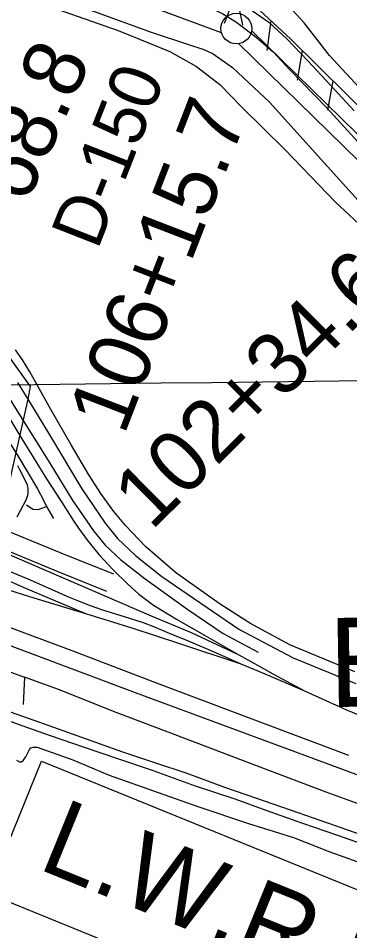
# Model space of a CAD drawing. Extents: x 3715084 to 3753216, y 488173 to 513963.
# Drawn here: x 3722098 to 3722638, y 498796 to 500282 of the extents above; entities that cross this region are included whole.
import ezdxf

# ---------------------------------------------------------------- set-up
doc = ezdxf.new("R2010")
doc.units = 0
for name, color, linetype in [('V-FLOD-BASE', 7, 'Continuous'), ('V-GRID-MAJR', 7, 'Continuous'), ('V-LEVE-TOET', 7, 'Continuous'), ('V-RAIL-TRAK', 7, 'Continuous'), ('V-RIVR-RANG', 7, 'Continuous'), ('V-RIVR-RANG-IDEN', 7, 'Continuous'), ('V-ROAD-CNTR', 7, 'Continuous'), ('V-RRAP-FSHR', 7, 'Continuous'), ('V-SITE-OTLN', 7, 'Continuous'), ('V-SITE-VEGE', 7, 'Continuous'), ('V-SURV-IDEN', 7, 'Continuous'), ('V-SURV-LINE', 7, 'Continuous'), ('V-TOPO-GNAM-IDEN', 7, 'Continuous'), ('V-TOPO-SHOR', 7, 'Continuous'), ('V-TOPO-WATR-IDEN', 7, 'Continuous')]:
    doc.layers.add(name, color=color, linetype=linetype)

msp = doc.modelspace()

# ---------------------------------------------------------------- linework, layer by layer
at = {"layer": 'V-FLOD-BASE'}
msp.add_lwpolyline([(3721354.051, 500735.405), (3721503.6550000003, 500674.19), (3721616.043, 500624.451), (3721750.253, 500566.103), (3721896.302, 500502.113), (3722014.554, 500452.484), (3722117.367, 500407.97500000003), (3722199.265, 500372.09), (3722243.313, 500357.139), (3722302.3140000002, 500338.863), (3722369.511, 500316.685), (3722399.9790000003, 500304.18200000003), (3722430.949, 500288.982), (3722451.484, 500276.74100000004), (3722460.182, 500270.13800000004), (3722485.358, 500251.219), (3722513.794, 500226.946), (3722540.06, 500198.12), (3722600.495, 500136.261), (3722650.953, 500080.901)], dxfattribs=at)
at = {"layer": 'V-GRID-MAJR'}
msp.add_spline([(3719277.161, 499651.167), (3724559.356, 499715.322), (3729841.541, 499780.245), (3735123.717, 499845.93700000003), (3740405.883, 499912.396), (3745688.039, 499979.624), (3750970.185, 500047.621), (3750970.186, 500047.621)], degree=3, dxfattribs=at)
at = {"layer": 'V-LEVE-TOET'}
for points in [[(3720179.593, 501167.86100000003), (3720304.218, 501115.194), (3720443.535, 501049.273), (3720609.5270000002, 500980.25200000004), (3720771.923, 500910.712), (3720950.632, 500837.42), (3721109.843, 500769.172), (3721268.537, 500704.525), (3721370.967, 500656.39900000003), (3721469.29, 500610.901), (3721591.1750000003, 500559.988), (3721710.311, 500511.278), (3721874.223, 500433.194), (3722033.844, 500367.20900000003), (3722177.073, 500309.034), (3722316.0870000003, 500258.89900000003), (3722373.752, 500239.697), (3722400.0810000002, 500231.175), (3722415.562, 500223.8), (3722446.661, 500201.835), (3722506.846, 500145.233), (3722601.332, 500040.56), (3722665.858, 499969.152)], [(3722479.5700000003, 500293.832), (3722505.856, 500275.83400000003), (3722535.2490000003, 500248.64900000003), (3722569.545, 500212.757), (3722605.481, 500173.74100000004), (3722644.643, 500131.175)]]:
    msp.add_lwpolyline(points, dxfattribs=at)
at = {"layer": 'V-RAIL-TRAK'}
for points in [[(3720331.13, 500168), (3720500.807, 500094.989), (3720658.671, 500026.267), (3720805.599, 499963.2), (3720958.009, 499896.628), (3721103.132, 499833.527), (3721225.492, 499781.273), (3721513.0500000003, 499654.11600000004), (3721780.551, 499537.855), (3722047.557, 499423.843), (3722314.5810000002, 499308.928), (3722379.616, 499281.74700000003), (3722429.239, 499258.33), (3722456.9990000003, 499245.776), (3722487.551, 499228.76300000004), (3722512.631, 499214.804), (3722564.145, 499186.912)], [(3720714.538, 499959.20900000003), (3720850.106, 499900.43700000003), (3721073.913, 499804.097), (3721268.176, 499719.376), (3721405.556, 499660.18700000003), (3721526.562, 499607.905), (3721636.1920000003, 499560.82), (3721735.387, 499516.693), (3721849.585, 499466.538), (3722018.793, 499394.422), (3722110.242, 499354.207), (3722207.811, 499312.756)], [(3720703.555, 499931.928), (3720820.0100000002, 499881.815), (3721010.196, 499797.919), (3721214.484, 499707.973), (3721455.126, 499604.284), (3721733.9960000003, 499483.278), (3721884.524, 499420.732), (3721914.556, 499407.32), (3721942.282, 499396.568), (3721965.889, 499388.898), (3722002.653, 499377.417), (3722048.063, 499362.043), (3722096.168, 499347.17), (3722123.409, 499338.21400000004), (3722207.811, 499312.756), (3722284.511, 499288.954), (3722357.153, 499265.074), (3722460.44, 499230.952)], [(3721019.975, 499840.966), (3721233.3170000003, 499749.387), (3721365.702, 499691.908), (3721533.556, 499619.767), (3721664.5870000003, 499562.264), (3721833.361, 499489.23600000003), (3722021.693, 499408.01), (3722064.455, 499389.427), (3722113.566, 499369.16000000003), (3722180.9080000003, 499339.31200000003), (3722194.542, 499334.159), (3722214.9990000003, 499325.978), (3722235.441, 499318.699), (3722279.012, 499305.092), (3722301.7, 499298.30700000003), (3722318.5160000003, 499291.86), (3722343.987, 499281.06700000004), (3722374.453, 499268.564), (3722419.029, 499249.563), (3722460.44, 499230.952), (3722502.274, 499213.704), (3722564.145, 499186.912), (3722627.401, 499158.343), (3722685.167, 499133.73)], [(3722077.2430000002, 499641.419), (3722104.254, 499597.27), (3722144.294, 499532.162), (3722168.469, 499494.727), (3722188.0130000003, 499463.517), (3722196.363, 499451.495), (3722210.723, 499431.919), (3722230.122, 499408.37700000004), (3722252.693, 499383.993), (3722276.14, 499360.982), (3722294.509, 499344.186), (3722318.305, 499326.594), (3722355.74, 499303.396), (3722399.987, 499278.075), (3722456.9990000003, 499245.776)], [(3722067.824, 499158.664), (3722140.491, 499133.208), (3722193.643, 499113.919), (3722267.676, 499087.814), (3722319.892, 499070.311), (3722372.335, 499052.59), (3722433.89, 499030.306), (3722485.669, 499011.89400000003), (3722553.1, 498989.045), (3722603.286, 498971.506), (3722665.052, 498949.901)], [(3722055.63, 499147.603), (3722105.589, 499130.06), (3722150.328, 499114.22000000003), (3722205.73, 499095.20300000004), (3722259.771, 499076.609), (3722314.481, 499058.255), (3722386.0300000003, 499032.325), (3722450.724, 499011.001), (3722500.923, 498992.786), (3722560.88, 498971.37200000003), (3722617.423, 498951.699), (3722674.64, 498932.039)]]:
    msp.add_lwpolyline(points, dxfattribs=at)
at = {"layer": 'V-RIVR-RANG'}
msp.add_line((3722433.9820000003, 500274.22300000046), (3722666.508, 500870.4910000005), dxfattribs=at)
at = {"layer": 'V-ROAD-CNTR'}
for points in [[(3720251.6783072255, 500219.6346124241), (3720308.6642738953, 500190.63727090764), (3720375.5829743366, 500156.585244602), (3720540.0271052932, 500080.3801856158), (3720665.4403785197, 500024.9046668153), (3720706.9172404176, 500008.49372954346), (3720843.506440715, 499949.191713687), (3721011.286575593, 499878.08507093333), (3721152.799076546, 499819.4778442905), (3721290.7920817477, 499757.6898569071), (3721410.819299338, 499707.1985587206), (3721530.781916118, 499653.69657235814), (3721581.56070035, 499631.33057269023), (3721759.180182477, 499553.09836033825), (3721970.3879949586, 499460.0875790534), (3722057.2200908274, 499424.38022048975), (3722162.6836148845, 499381.0096295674), (3722241.9095104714, 499349.3547025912)], [(3722097.237, 499688.938), (3722113.718, 499661.825), (3722147.387, 499606.431), (3722201.794, 499515.794), (3722239.807, 499459.737), (3722259.437, 499434.798), (3722289.393, 499406.636), (3722331.762, 499373.237), (3722457.2290000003, 499287.37700000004), (3722545.6920000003, 499240.492), (3722647.742, 499198.653)], [(3724721.5925178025, 498318.2013374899), (3722898.611163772, 498957.6830585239), (3722289.22838254, 499183.4286070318), (3721129.602701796, 499619.490734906)], [(3722097.154913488, 499553.62691189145), (3722100.310142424, 499547.42194799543), (3722111.263800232, 499525.88859402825), (3722112.517386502, 499522.5469335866), (3722113.3979872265, 499519.12012826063), (3722113.9057156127, 499515.61753823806), (3722114.0341783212, 499512.0866489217), (3722113.7859046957, 499508.55748530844), (3722113.154824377, 499505.0625551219), (3722112.1545054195, 499501.67248335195), (3722110.8440464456, 499498.5110233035), (3722095.649951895, 499469.77940974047)], [(3722081.915745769, 499446.66214088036), (3722173.9543851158, 499408.8123704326), (3722253.040489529, 499377.21329740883)]]:
    msp.add_lwpolyline(points, dxfattribs=at)
at = {"layer": 'V-RRAP-FSHR'}
for p, q in [((3722453.522, 500318.373), (3722463.264, 500270.52400000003)), ((3722509.4050000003, 500277.787), (3722502.596, 500229.433)), ((3722560.057, 500229.482), (3722551.8310000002, 500181.349)), ((3722609.815, 500180.24700000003), (3722601.589, 500132.114))]:
    msp.add_line(p, q, dxfattribs=at)
for points in [[(3724699.7800000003, 499231.582), (3724234.565, 499410.511), (3724074.774, 499465.947), (3723910.948, 499525.384), (3723785.557, 499586.533), (3722795.661, 500019.571), (3722760.251, 500033.657), (3722724.847, 500066.423), (3722541.517, 500247.827), (3722476.702, 500308.298), (3722393.071, 500344.648), (3721960.203, 500508.445), (3721362.184, 500763.99100000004), (3720460.911, 501156.501), (3720298.304, 501222.873), (3720229.921, 501264.912), (3720222.529, 501299.679)], [(3722824.319, 500007.034), (3722795.661, 500019.571), (3722760.251, 500033.657), (3722724.847, 500066.423), (3722541.517, 500247.827), (3722476.702, 500308.298), (3722393.071, 500344.648), (3721960.203, 500508.445), (3721362.184, 500763.99100000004), (3720460.911, 501156.501), (3720298.304, 501222.873), (3720229.921, 501264.912), (3720222.529, 501299.679)]]:
    msp.add_lwpolyline(points, dxfattribs=at)
at = {"layer": 'V-SITE-OTLN'}
msp.add_lwpolyline([(3721610.727, 500476.558), (3721508.9, 500234.186), (3721552.287, 500172.613), (3721570.951, 500156.45), (3721741.701, 500056.927), (3721760.257, 500046.26900000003), (3721989.84, 499845.09), (3722040.461, 499789.161), (3722117.748, 499682.35000000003), (3722113.718, 499661.825), (3722086.94, 499540.62200000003), (3722077.251, 499496.20900000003), (3722068.324, 499483.19), (3722044.823, 499464.39), (3722009.753, 499474.732), (3721224.957, 499821.32300000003), (3721022.99, 499907.071)], dxfattribs=at)
at = {"layer": 'V-SITE-VEGE'}
for p, q in [((3722116.523, 499091.35499999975), (3722118.727, 499094.103)), ((3722118.727, 499094.103), (3722122.543, 499095.07800000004)), ((3722122.543, 499095.07800000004), (3722125.696, 499095.365)), ((3722125.696, 499095.365), (3722129.088, 499094.977)), ((3722129.088, 499094.977), (3722186.77, 499074.64900000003)), ((3722106.7770000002, 499074.137), (3722110.656, 499079.701)), ((3722110.656, 499079.701), (3722113.111, 499084.936)), ((3722113.111, 499084.936), (3722116.523, 499091.35499999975)), ((3722095.271, 499074.143), (3722100.293, 499071.081)), ((3722100.293, 499071.081), (3722103.447, 499071.368)), ((3722103.447, 499071.368), (3722106.7770000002, 499074.137)), ((3722186.77, 499074.64899999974), (3722207.69, 499065.8)), ((3722207.69, 499065.8), (3722246.342, 499049.846)), ((3722246.342, 499049.8459999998), (3722390.554, 498998.68499999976)), ((3722390.554, 498998.685), (3722472.972, 498970.707)), ((3722472.972, 498970.707), (3722546.038, 498947.9659999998)), ((3722546.038, 498947.9659999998), (3722605.3540000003, 498924.73499999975)), ((3722605.3540000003, 498924.73499999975), (3722695.298, 498892.39099999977))]:
    msp.add_line(p, q, dxfattribs=at)
for points in [[(3721724.012, 500148.555), (3721730.062, 500186.115), (3721748.719, 500248.733), (3721783.838, 500323.392), (3721808.904, 500381.169), (3721821.0500000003, 500406.666), (3721826.742, 500415.798), (3721833.404, 500421.338), (3721839.691, 500422.811), (3721845.989, 500423.835), (3721859.5530000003, 500422.288), (3721908.647, 500402.922), (3722063.407, 500331.433), (3722260.987, 500262.114), (3722345.111, 500227.626), (3722387.9760000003, 500203.632), (3722426.435, 500174.134), (3722462.795, 500136.48), (3722532.22, 500068.324), (3722614.169, 499982.364), (3722668.3510000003, 499932.865)], [(3722659.2460000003, 500161.97500000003), (3722604.484, 500221.265), (3722563.241, 500274.777), (3722531.0670000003, 500309.693)], [(3722645.903, 499217.571), (3722539.941, 499261.57), (3722475.202, 499296.878), (3722424.965, 499328.853), (3722354.063, 499379.836), (3722305.4390000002, 499421.76900000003), (3722272.747, 499456.335), (3722253.8170000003, 499478.984), (3722233.44, 499506.566), (3722212.9760000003, 499538.66000000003), (3722184.077, 499587.286), (3722151.397, 499644.863), (3722126.643, 499689.055), (3722116.8370000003, 499706.463), (3722105.182, 499726.093), (3722093.598, 499742.113)]]:
    msp.add_lwpolyline(points, dxfattribs=at)
at = {"layer": 'V-SURV-LINE'}
for points in [[(3722429.1476082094, 500258.06374399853), (3722229.3442902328, 500332.4302392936)], [(3722477.8635045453, 500261.8978983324), (3722721.541392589, 500023.26420227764)], [(3722700.555658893, 500001.8259416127), (3722456.8780626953, 500240.4593518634)]]:
    msp.add_lwpolyline(points, dxfattribs=at)
msp.add_circle((3722453.10042, 500265.15374000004), 25, dxfattribs=at)
at = {"layer": 'V-TOPO-SHOR'}
for points in [[(3721534.867, 500138.745), (3721627.918, 500084.422), (3721683.912, 500054.01900000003), (3721701.2260000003, 500043.06), (3721722.7260000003, 500027.735), (3721782.13, 499979.95300000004), (3721856.4420000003, 499921.851), (3721936.762, 499853.602), (3721996.718, 499794.884), (3722024.849, 499754.71400000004), (3722057.267, 499705.048), (3722098.552, 499638.791), (3722149.3570000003, 499557.664), (3722185.734, 499497.813), (3722220.5640000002, 499447.166), (3722239.813, 499424.271), (3722264.897, 499400.463), (3722304.4930000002, 499369.065), (3722374.1950000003, 499319.42600000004), (3722431.721, 499280.50200000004), (3722488.741, 499250.12)], [(3721839.077, 499881.84), (3721888.311, 499847.204), (3721919.27, 499820.086), (3721950.33, 499787.84), (3721970.286, 499763.934), (3721998.299, 499729.92100000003), (3722021.185, 499695.80700000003), (3722051.272, 499642.678), (3722099.238, 499566.97000000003), (3722129.631, 499515.897), (3722139.563, 499497.272), (3722144.204, 499487.10000000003), (3722155.526, 499467.476)], [(3722636.079, 499081.811), (3722482.95, 499138.895), (3722328.8910000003, 499197.314), (3722190.278, 499250.163), (3722022.6040000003, 499312.833), (3721879.015, 499366.489), (3721708.1580000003, 499430.452), (3721634.572, 499456.57), (3721492.307, 499511.604), (3721352.3510000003, 499563.976), (3721225.396, 499620.656), (3721105.403, 499667.092), (3720991.829, 499713.396)], [(3722111.6550000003, 499489.897), (3722122.057, 499482.572), (3722130.96, 499482.058), (3722135.037, 499483.504), (3722144.204, 499487.10000000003)], [(3721798.463, 499324.14900000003), (3721941.3540000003, 499270.378), (3722075.3850000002, 499221.052), (3722108.549, 499209.05100000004), (3722106.054, 499164.435)], [(3723779.79, 498603.51900000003), (3723676.352, 498639.375), (3723546.474, 498683.81700000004), (3723422.0500000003, 498726.108), (3723285.348, 498773.579), (3723159.119, 498815.835), (3723009.218, 498869.37), (3722849.349, 498924.971), (3722747.06, 498965.88), (3722688.86, 498989.581), (3722599.362, 499022.163), (3722487.574, 499064.243), (3722342.148, 499119.668), (3722257.627, 499151.441), (3722163.974, 499188.905), (3722108.549, 499209.05100000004)]]:
    msp.add_lwpolyline(points, dxfattribs=at)
at = {"layer": 'V-TOPO-WATR-IDEN'}
msp.add_line((3722001.16819057, 498876.8247659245), (3722696.8715213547, 498593.4551917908), dxfattribs=at)
msp.add_lwpolyline([(3721781.516564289, 498994.9219852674), (3722081.6616703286, 498938.205217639), (3722136.2556967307, 499072.23799779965), (3722727.61375126, 498831.3669422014), (3722673.019724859, 498697.33416204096), (3722936.5255493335, 498524.4654973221)], dxfattribs=at)

# ---------------------------------------------------------------- texts
at = {"layer": 'V-RIVR-RANG-IDEN'}
msp.add_text('D-150', height=83, rotation=68.55432571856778, dxfattribs=at).set_placement((3722227.152143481, 499903.27871804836))
at = {"layer": 'V-SURV-IDEN'}
for s, height, rotation, p in [('108+68.8', 99.99999999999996, 65.90138889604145, (3721988.143408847, 499701.5846143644)), ('106+15.7', 100.00000000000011, 68.88805557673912, (3722270.2480142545, 499601.36499050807)), ('102+34.6', 99.99999999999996, 44.90194442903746, (3722315.0290362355, 499446.4662424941))]:
    msp.add_text(s, height=height, rotation=rotation, dxfattribs=at).set_placement(p)
at = {"layer": 'V-TOPO-GNAM-IDEN'}
msp.add_text('Braithwaite', height=145.00000199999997, rotation=0.9179915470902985, dxfattribs=at).set_placement((3722604.132, 499160.358))
at = {"layer": 'V-TOPO-WATR-IDEN'}
msp.add_text('L.W.R.P.', height=124.49949300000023, rotation=337.83796045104, dxfattribs=at).set_placement((3722127.7181130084, 498898.1648990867))

doc.saveas('drawing.dxf')
